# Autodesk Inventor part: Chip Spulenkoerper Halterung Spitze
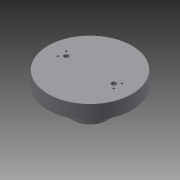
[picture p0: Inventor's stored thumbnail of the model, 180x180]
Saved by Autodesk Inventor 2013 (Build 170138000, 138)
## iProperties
Created: 2013-02
Part Number: Chip Spulenkoerper Halterung Spitze
Material: Allgemein
Document SubType Name: Modeling
Designer: Hübner
Density: 1 g/cm^3
Author: Hübner
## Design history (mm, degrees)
sketch "Skizze1"
  geometry: C1 r 30 at (0, 0); 1 further point
  constraints: 1 centre point, 1 coincident
  dimensions: "d0" = 60 diameter of C1
extrude "Extrusion1" new body sketch "Skizze1" distance "d1" = 10; taper "d2" = 0 deg
sketch "Skizze2"
  geometry: C1 r 30 at (0, 0) reference; C2 r 12.5 at (0, 0)
  constraints: 1 centre point, 1 coincident
  dimensions: "d3" = 25 diameter of C2
extrude "Extrusion2" join sketch "Skizze2" distance "d4" = 15; taper "d5" = 0 deg
sketch "Skizze3"
  geometry: L1 (-17, 0)-(17, 0); C1 r 30 at (0, 0) reference; 1 further point
  constraints: 2 end point, 1 coincident, 1 horizontal, 1 midpoint
  dimensions: "d7" = 34 distance of L1.end L1.start
hole "Bohrung1" sketch "Skizze3" at (-17, 0), (17, 0) diameter "d9" = 3.242; stored, may be unused: countersink angle "d13" = 90 deg, drill point angle "d15" = 118 deg; dims "d10" = 6, "d11" = 4, "d12" = 2, "d14" = 6
hole "Bohrung2" diameter "d18" = 3; stored, may be unused: countersink angle "d22" = 60 deg, drill point angle "d24" = 120 deg; dims "d19" = 6, "d20" = 6.3, "d21" = 2, "d23" = 5, "d27" = 10, "d28" = 10
sketch "Skizze4"
  geometry: L1 (-20, 3)-(20, 3); L2 (20, 3)-(20, -3); L3 (20, -3)-(-20, -3); L4 (-20, -3)-(-20, 3); C1 r 30 at (0, 0); 2 further points
  constraints: 8 end point, 2 midpoint, 2 parallel, 1 centre point, 1 horizontal, 1 horizontal alignment, 1 perpendicular, 1 vertical alignment
  dimensions: "d26" = 40 distance of L2.end L3.end; "d29" = 6 distance of L1.end L2.end
hole "Bohrung3" sketch "Skizze4" at (-20, 3), (-20, -3), (20, 3), (20, -3) diameter "d35" = 1.5; stored, may be unused: drill point angle "d30" = 118 deg, countersink angle "d31" = 90 deg; dims "d25" = 6, "d32" = 2, "d33" = 4, "d34" = 8
node "Volumenkörper1"
